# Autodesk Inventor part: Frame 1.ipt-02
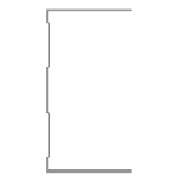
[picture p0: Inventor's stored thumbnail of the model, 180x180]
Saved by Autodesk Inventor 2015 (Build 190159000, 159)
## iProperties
IsCustomPart: 1
Created: 2015-04
Part Number: Frame 1.ipt-02
Material: Aluminum 6061
Description: Kévin Novo
Document SubType Name: Modeling
Standard: Kevin
Designer: suporte
Standards Organization: Kevin
Language: en-US
Size Designation: (Unnamed 2)
Categories: <MemberInstance><Categories><Category DisplayName="Structural Shapes" InternalName="089c4875-fa83-4c05-b084-43b9cc11f5ed" Mnemonic="GRDR"><CategoryParameter Dis
Density: 2.7 g/cm^3
Appearance: Aluminum - Flat
_CCFamilyMember: 2
_CCFamilyDisplayName: Kévin - Kévin Novo
_FrameMemberDoc: Frame Member File
_Version: 15.0.0
_GetPNFromCC: 1
G_W: 50,000 mm
G_H: 75,000 mm
G_L: 470,645 mm
+C6D07C4E-F784-4905-9E85-D001DAC4732C+CUTDETAIL2: Miter 67,49 deg
+9BC56BD3-3601-4756-9CD3-DFE412EE9504+CUTDETAIL3: Miter 67,51 deg
Author: suporte
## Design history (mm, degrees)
node "Start Plane"
node "End Plane"
sketch "Sketch"
  geometry: L1 (24.7, 37.5)-(24.7, 36.9); L2 (24.7, 36.9)-(-24.7, 36.9); L3 (-24.7, -36.9)-(24.7, -36.9); L4 (24.7, -36.9)-(24.7, -37.5); L5 (24.7, -37.5)-(-25.3, -37.5); L6 (-25.3, 37.5)-(24.7, 37.5); L7 (-24.7, 36.9)-(-24.7, 31.9); L8 (-24.7, 31.9)-(-23.3, 30.5); L9 (-23.3, 30.5)-(-23.3, 10.934); L10 (-23.3, 10.934)-(-24.7, 9.534); L11 (-24.7, 9.534)-(-24.7, -9.534); L12 (-24.7, -9.534)-(-23.3, -10.934); L13 (-23.3, -10.934)-(-23.3, -30.5); L14 (-23.3, -30.5)-(-24.7, -31.9); L15 (-24.7, -31.9)-(-24.7, -36.9); L16 (-25.3, -37.5)-(-25.3, -31.651); L17 (-25.3, -31.651)-(-23.9, -30.251); L18 (-23.9, -30.251)-(-23.9, -11.183); L19 (-23.9, -11.183)-(-25.3, -9.783); L20 (-25.3, -9.783)-(-25.3, 9.783); L21 (-25.3, 9.783)-(-23.9, 11.183); L22 (-23.9, 11.183)-(-23.9, 30.251); L23 (-23.9, 30.251)-(-25.3, 31.651); L24 (-25.3, 31.651)-(-25.3, 37.5); L25 (-25.3, 0)-(30.37, 0); 3 further points
  constraints: 50 end point, 10 point on line, 9 parallel, 5 perpendicular, 4 equal length, 3 midpoint, 3 vertical, 2 vertical alignment, 1 collinear, 1 horizontal, 1 horizontal alignment
  dimensions: "d3" = 0.6 distance of L1.start L1.end (= d6); "d5" = 75 distance between parallel lines of L5 L6; "d6" = 0.6 distance between parallel lines of L24 L7 (= d8); "d7" = 0.6 distance between parallel lines of L8 L23 (= d8); "d8" = 0.6 distance between parallel lines of L22 L9 (= d12); "Espessura" = 0.6 distance between parallel lines of L17 L14; "d10" = 0.6 distance between parallel lines of L13 L18 (= Espessura); "d11" = 0.6 distance between parallel lines of L12 L19 (= Espessura); "d12" = 0.6 distance between parallel lines of L21 L10 (= d11); "d13" = 5 distance of L2.end L7.end; "d15" = 135 deg angle of L9 L8; "d16" = 2 distance between parallel lines of L24 L9; "d17" = 50 distance of L6.start L1.start
extrude "Body" join sketch "Sketch" stored distance "d24" = 0.13; taper "d25" = 0 deg
node "Driven Length"
  sketch "Sketch10"
    geometry: L1 (0, 0)-(10, 0) reference
    constraints: 2 end point, 1 horizontal
  workplane "Work Plane7"
  sketch "Sketch11"
    geometry: L1 (-2, -36.226)-(12, -36.226) reference; L2 (-2, 434.419)-(12, 434.419) reference
    dimensions: "d27" = 470.64466 distance between parallel lines of L1 L2 (derived)
workplane "Work Plane9"
split "Split2"
workplane "Work Plane10"
split "Split3"
body "Solid1"
other parameters: "tamanho" = 398.15728, "G_OFFSET_START" = 36.22585 [user parameter; used in 1 equation term], "G_OFFSET_END" = 36.26152 [user parameter; used in 1 equation term], "d22" = -36.22585 (= -G_OFFSET_START), "d23" = 434.41881 (= tamanho + G_OFFSET_END), "G_L" = 470.64466 (= d27) [user parameter], "d34" = 90 deg
